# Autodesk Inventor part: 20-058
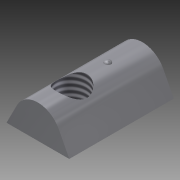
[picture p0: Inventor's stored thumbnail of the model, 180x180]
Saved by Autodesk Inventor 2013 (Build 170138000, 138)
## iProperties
Created: 2004-10
Part Number: 20-058
Material: Stahl (hohe Festigk., niedr. Legier.)
Document SubType Name: Modeling
Designer: Autodesk, Inc.
Manufacturer: Standard
Standards Organization: Custom
Description: NUT, T SLOT, STANDARD, 40 SERIES, M8
Catalog Web Link: http://www.parker.com/ead/cm1.asp?cmid=809
Vendor: PARKER IPS
Mass: 10.738 g
Surface Area: 10.2004 cm^2
Volume: 1.36964 cm^3
Density: 7.84 g/cm^3
CAGE: 1LJX3
Dept. ID: Product Design
Description #2: ---
Finish #1: ---
Finish #2: ---
Material ID: ---
Project Number: ---
Author: Autodesk, Inc.
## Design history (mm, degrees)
derived "20-XXX TSlot Nuts.ipt"
body "Solid1"
tag "TaggingFeature2"
feature "Solid1::20-XXX TSlot Nuts.ipt" dims "ScaleForDerivedMember" = 10
